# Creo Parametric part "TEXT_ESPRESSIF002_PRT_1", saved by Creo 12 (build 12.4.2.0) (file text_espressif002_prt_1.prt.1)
Units: Custom; MM, KILOGRAM, SECS

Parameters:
  PTC_WM_ITERATION = "0"
  PTC_WM_VERSION = "-.0"
  PTC_WM_LIFECYCLE_STATE = "In Work"
  PTC_WM_LIFECYCLE = "MO_CADDocument"
  PTC_WM_CREATED_BY = "Maximilian Roepper (Z0017RMS: MO)"
  PTC_WM_CREATED_ON = "18-Sep-26 11:36:42 AM"
  PTC_WM_MODIFIED_BY = "Maximilian Roepper (Z0017RMS: MO)"
  PTC_WM_MODIFIED_ON = "18-Sep-26 11:36:46 AM"
  PDMLINKNUMBER = "PDM000071454762"
  PTC_WM_NAME = "text_espressif002_prt_1.prt"
  PTC_WM_NUMBER = "PDM000071454762"

Other parameters: WEIGHT, WEIGHT_FACTOR, WEIGHT_ADD, _MASS_TEMP, _DIFF_TEMP, MC_ERRORS, SUPPLIER

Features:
  1. coordinate system
  2. datum plane "PRT_YZ"
  3. datum plane "PRT_XY"
  4. datum plane "PRT_XZ"
  5. coordinate system
  6. datum axis
  7. datum axis
  8. datum axis
  9. coordinate system
  10. imported feature
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
Other named items: PRT, SIEMENS_MO, DRW_VIEW_ORG, PRT_X, PRT_Y, PRT_Z, CS0, ROUGH_GROB

Layers: 00_STD_CSYS-KSYS, 01_STD_PLANES-EBENEN, 02_STD_AXES-ACHSEN, 03_STD_CSYS-KSYS, 24_IMPORT_FEAT-IMPORT_KE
